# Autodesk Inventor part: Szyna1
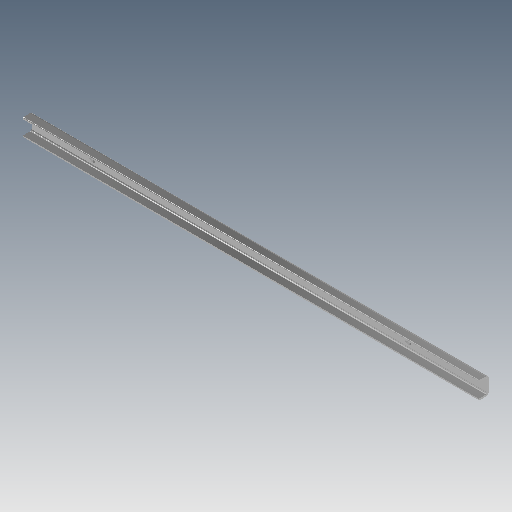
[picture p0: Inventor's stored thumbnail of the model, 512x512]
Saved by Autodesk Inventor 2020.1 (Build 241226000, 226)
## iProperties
Created: 2005-10
Part Number: Szyna1
Document SubType Name: Modeling
Designer: F.Stasiak
Density: 1 g/cm^3
Material: Ogólny
Appearance: Chrom — polerowany
Manager: www.cadconsulting.pl
Company: Fabian Stasiak CAD Consulting
Author: F.Stasiak
Subject: Zbiór ćwiczeń. Autodesk Inventor 2020. Kurs podstawowy
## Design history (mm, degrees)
sketch "Szkic1"
  geometry: L1 (-282.277, 97.752)-(-22.277, 97.752); L2 (-22.277, 97.752)-(-22.277, 87.752); L3 (-22.277, 87.752)-(-282.277, 87.752); L4 (-282.277, 87.752)-(-282.277, 97.752)
  constraints: 8 end point, 2 parallel, 1 horizontal, 1 perpendicular
  dimensions: "d0" = 260 distance of L1.start L1.end; "d1" = 10 distance of L3.end L1.start
extrude "Wyciągnięcie proste1" new body sketch "Szkic1" distance "d2" = 6; taper "d3" = 0 deg
fillet "Zaokrąglenie1" dims "d4" = 2
feature "Skorupa1" dims "d5" = 1
sketch "Szkic2"
  geometry: L1 (0, 0)-(0, 6) reference; L2 (260, 6)-(260, 0) reference; L3 (0, 3)-(260, 3); 2 further points
  constraints: 2 end point, 2 midpoint, 2 point on line
  dimensions: "d6" = 35 distance from line of L1 point (35, 3); "d7" = 180 distance of point (215, 3) point (35, 3)
hole "Otwór1" sketch "Szkic2" at (35, 3), (215, 3) diameter "d8" = 3.5; stored, may be unused: countersink angle "d12" = 120 deg, drill point angle "d14" = 118 deg; dims "d9" = 6, "d10" = 5, "d11" = 2, "d13" = 8
fillet "Zaokrąglenie2" dims "d15" = 0.5
node "Bryła1"
node "Korpusy bryłowe"
node "Korpusy powierzchniowe"
